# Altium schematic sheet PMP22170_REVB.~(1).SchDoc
size 431 x 279 mm; Date: Not shown in title block; ApprovedBy: Not shown in title block; CheckedBy: Not shown in title block; Author: Not shown in title block; CompanyName: Not shown in title block; Engineer: Not shown in title block; Organization: Not shown in title block; Address1: Not shown in title block; Address2: Not shown in title block; Address3: Not shown in title block; Address4: Not shown in title block; DocumentNumber: 1; Revision: Use project parameter SCH_Rev; SheetNumber: 1; SheetTotal: 1; PageSetup: Record=PageOptions¦CenterHorizontal=True¦CenterVertical=True¦PrintScale=1.00¦XCorrection=1.00¦YCorrection=1.00¦PrintKind=0¦BorderSize=5000000¦LeftOffset=0¦BottomOffset=0¦Orientation=2¦PaperLength=1000¦PaperWidth=1000¦Scale=100¦PaperSource=15¦PrintQuality=600¦MediaType=1¦DitherType=10¦PaperKind=Letter¦PrintScaleMode=1
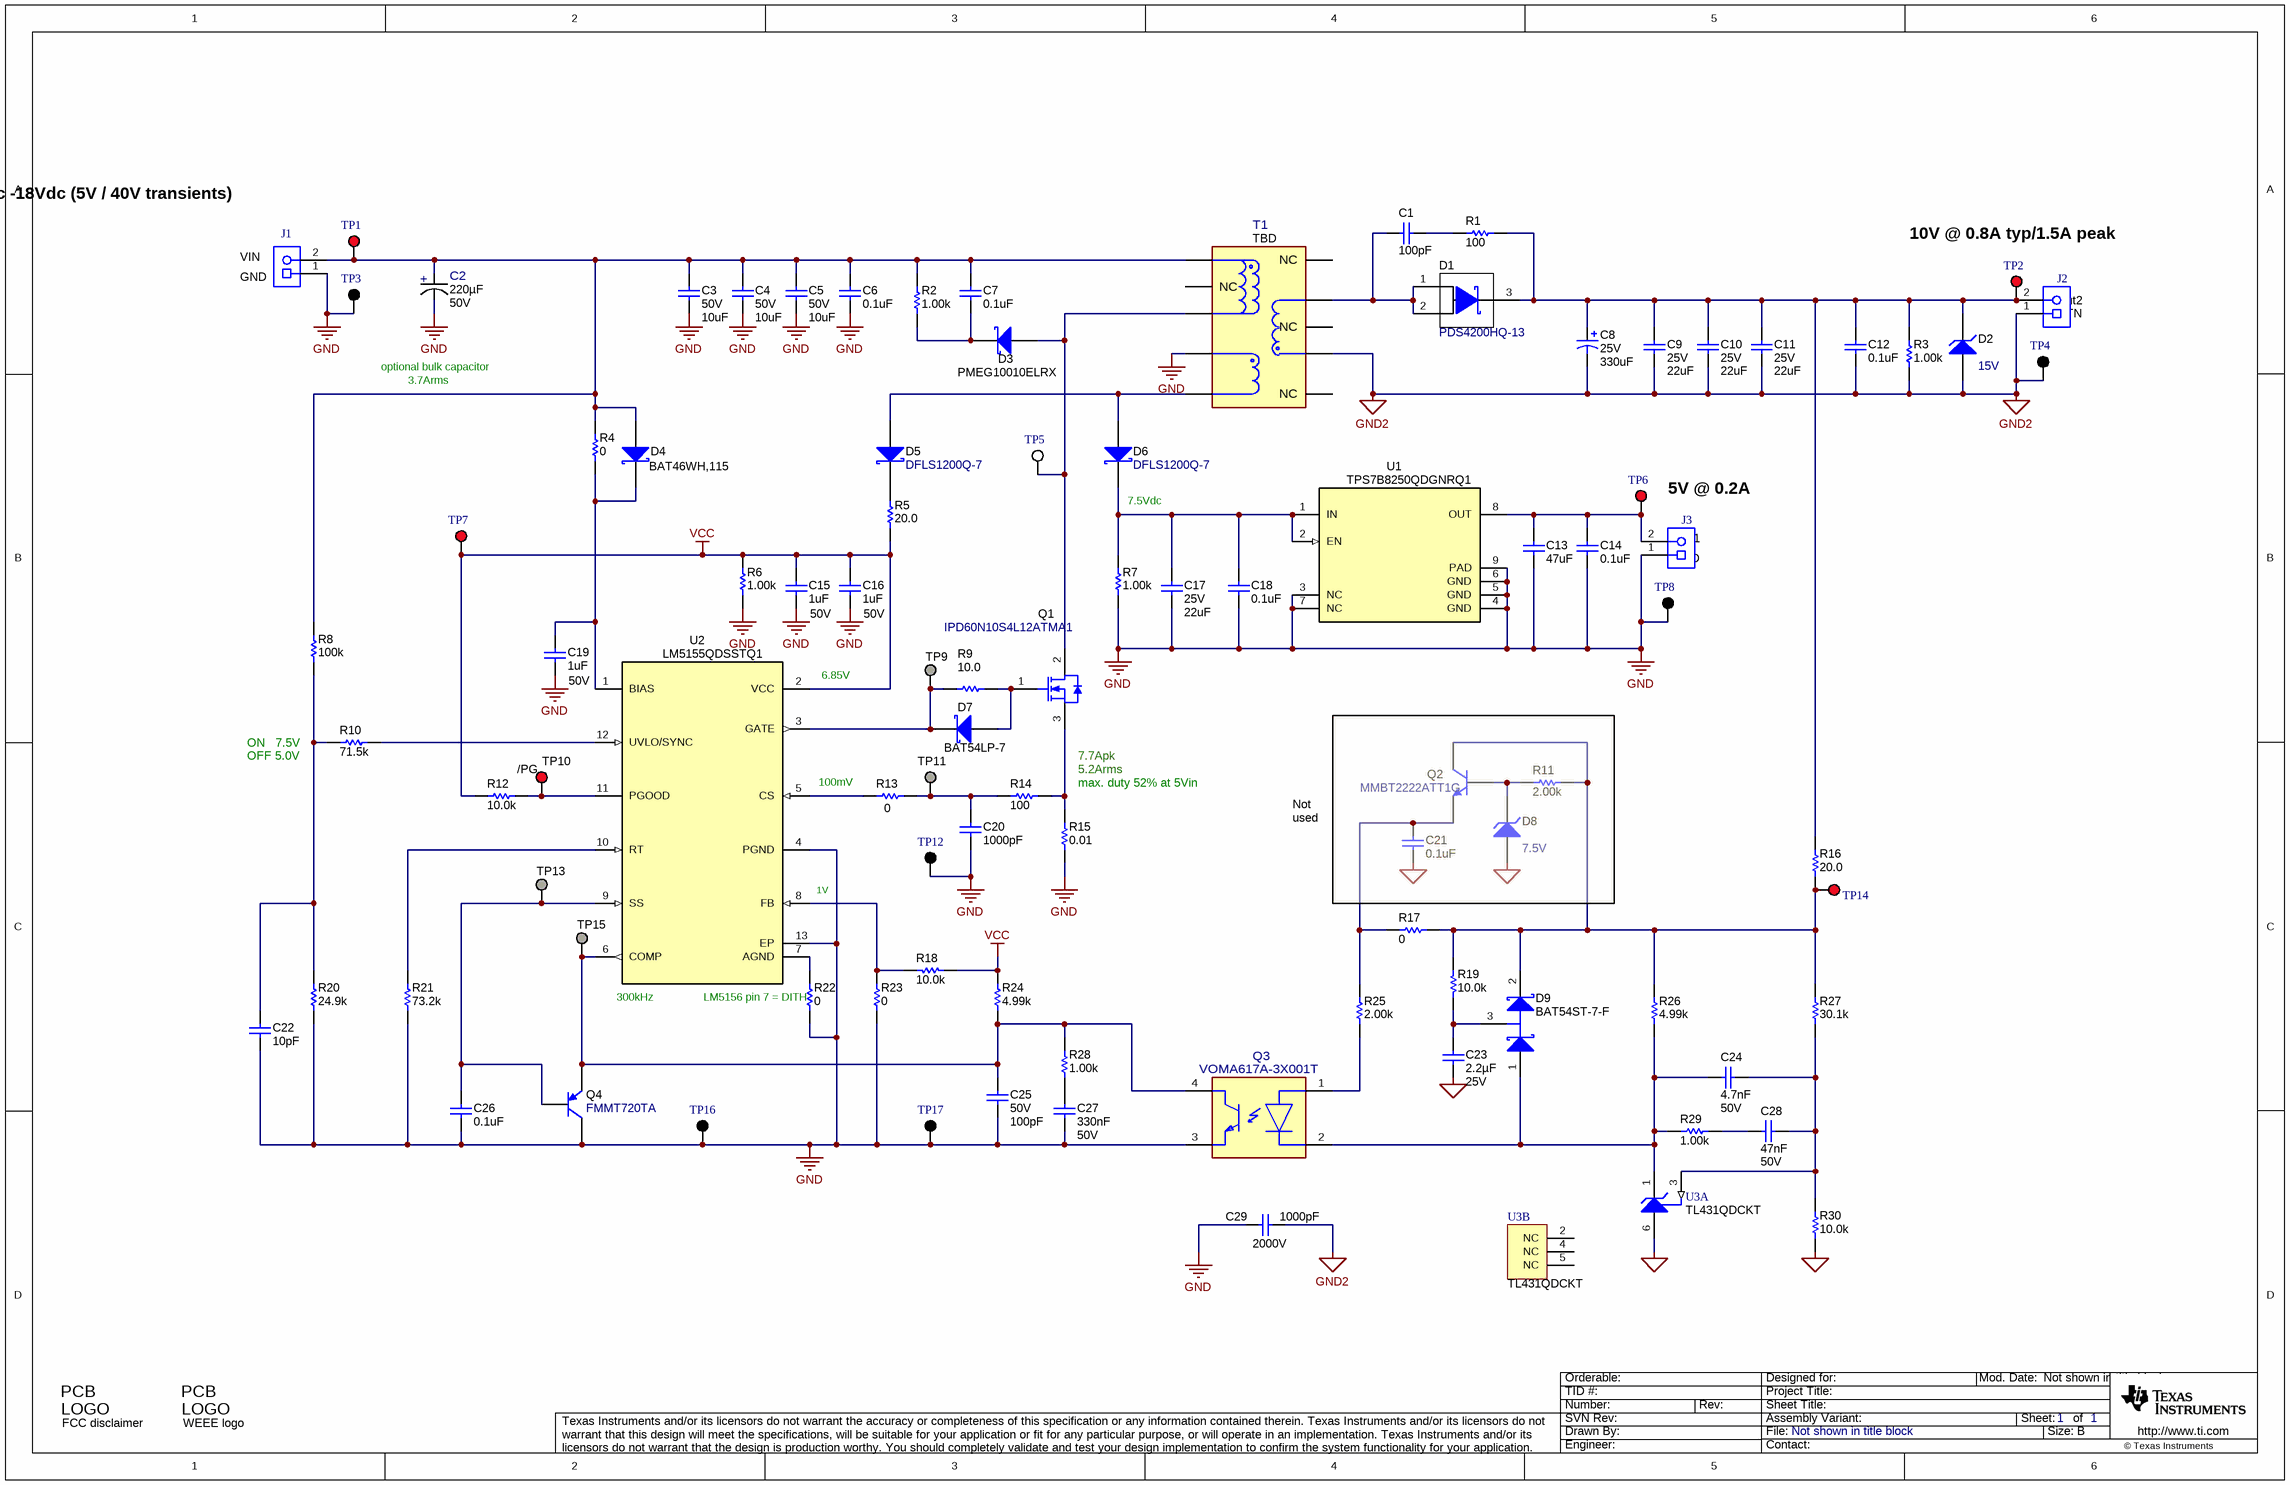
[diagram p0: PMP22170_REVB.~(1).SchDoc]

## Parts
C1  ValueDisplayed: 100pF  [0805_HV]  (hidden comment: Capacitor)
C2  Cap_F: 220µF  VDC_V: 50V  [FP-EEHZS1H221P_RADIAL_SMD-MFG]  (hidden comment: EEH-ZS1H221V)
C3  VDC_V: 50V  ValueDisplayed: 10uF  [1210_280]  (hidden comment: UMK325AB7106KMHT)
C4  VDC_V: 50V  ValueDisplayed: 10uF  [1210_280]  (hidden comment: UMK325AB7106KMHT)
C5  VDC_V: 50V  ValueDisplayed: 10uF  [1210_280]  (hidden comment: UMK325AB7106KMHT)
C6  ValueDisplayed: 0.1uF  [0603]  (hidden comment: Capacitor)
C7  ValueDisplayed: 0.1uF  [0603]  (hidden comment: Capacitor)
C8  VDC_V: 25V  ValueDisplayed: 330uF  [SM_RADIAL_10BMM]  (hidden comment: EEHZC1E331P)
C9  VDC_V: 25V  ValueDisplayed: 22uF  [1210_270]  (hidden comment: TMK325B7226KMHT)
C10  VDC_V: 25V  ValueDisplayed: 22uF  [1210_270]  (hidden comment: TMK325B7226KMHT)
C11  VDC_V: 25V  ValueDisplayed: 22uF  [1210_270]  (hidden comment: TMK325B7226KMHT)
C12  ValueDisplayed: 0.1uF  [0603]  (hidden comment: Capacitor)
C13  ValueDisplayed: 47uF  [1210_270]  (hidden comment: Capacitor)
C14  ValueDisplayed: 0.1uF  [0603]  (hidden comment: Capacitor)
C15  ValueDisplayed: 1uF  Value2: 50V  [0805_HV1]  (hidden comment: Capacitor)
C16  ValueDisplayed: 1uF  Value2: 50V  [0805_HV1]  (hidden comment: Capacitor)
C17  VDC_V: 25V  ValueDisplayed: 22uF  [1210_270]  (hidden comment: TMK325B7226KMHT)
C18  ValueDisplayed: 0.1uF  [0603]  (hidden comment: Capacitor)
C19  ValueDisplayed: 1uF  Value2: 50V  [0805_HV1]  (hidden comment: Capacitor)
C20  ValueDisplayed: 1000pF  [0603]  (hidden comment: Capacitor)
C21  ValueDisplayed: 0.1uF  [0603]  (hidden comment: Capacitor)
C22  ValueDisplayed: 10pF  [0603]  (hidden comment: Capacitor)
C23  Cap_F: 2.2µF  VDC_V: 25V  [0805_HV]  (hidden comment: CGA4J3X7R1E225K125AB)
C24  Cap_F: 4.7nF  VDC_V: 50V  [0603]  (hidden comment: GCM188R71H472KA37D)
C25  VDC_V: 50V  ValueDisplayed: 100pF  [0603]  (hidden comment: GCM1885C1H101JA16J)
C26  ValueDisplayed: 0.1uF  [0603]  (hidden comment: Capacitor)
C27  Cap_F: 330nF  VDC_V: 50V  [0603]  (hidden comment: CGA3E3X7R1H334K080AB)
C28  Cap_F: 47nF  VDC_V: 50V  [0603]  (hidden comment: CGA3E2X7R1H473K080AA)
C29  ValueDisplayed: 1000pF  Value2: 2000V  [1808]  (hidden comment: Capacitor)
D1  PDS4200HQ-13  [POWERDI5]
D2  value 15V  [SOD-123]  (hidden comment: MMSZ5245B-7-F)
D3  PartNumber: PMEG10010ELRX  [SOD-123W]  (hidden comment: DIODE_SCHOTTKY)
D4  PartNumber: BAT46WH,115  [SOD-123F]  (hidden comment: DIODE_SCHOTTKY)
D5  DFLS1200Q-7  [PowerDI123]
D6  DFLS1200Q-7  [PowerDI123]
D7  PartNumber: BAT54LP-7  [X1-DFN1006-2]  (hidden comment: DIODE_SCHOTTKY)
D8  value 7.5V  [SOD-123]  (hidden comment: MMSZ4693-HE3-08)
D9  PartNumber: BAT54ST-7-F  [SOT-523]  (hidden comment: DIODE_BAT54S)
J1  Receptacle_2x1  [TERM_BLK_ED555-2DS]  (value not drawn)
J2  Receptacle_2x1  [TERM_BLK_ED555-2DS]  (value not drawn)
J3  Receptacle_2x1  [TERM_BLK_ED555-2DS]  (value not drawn)
Logo1  FCC disclaimer  [FCC_disclaimer]  (no BOM)
Logo2  WEEE logo  [WEEE_Minimum]  (no BOM)
Q1  IPD60N10S4L12ATMA1  [DPAK]
Q2  MMBT2222ATT1G  [SOT-416]
Q3  VOMA617A-3X001T  [FP-VOMA617A-3X001T_SOP4-MFG]
Q4  FMMT720TA  [SOT-23]
R1  ValueDisplayed: 100  [1206]  (hidden comment: CRCW1206100RFKEAHP)
R2  ValueDisplayed: 1.00k  [1210]  (hidden comment: ERJ14NF1001U)
R3  ValueDisplayed: 1.00k  [1210]  (hidden comment: ERJ14NF1001U)
R4  ValueDisplayed: 0  [0603]  (hidden comment: Resistor)
R5  ValueDisplayed: 20.0  [0805_HV]  (hidden comment: CRCW080520R0FKEA)
R6  ValueDisplayed: 1.00k  [1210]  (hidden comment: ERJ14NF1001U)
R7  ValueDisplayed: 1.00k  [1210]  (hidden comment: ERJ14NF1001U)
R8  ValueDisplayed: 100k  [0603]  (hidden comment: CRCW0603100KFKEA)
R9  ValueDisplayed: 10.0  [0603]  (hidden comment: Resistor)
R10  ValueDisplayed: 71.5k  [0603]  (hidden comment: CRCW060371K5FKEA)
R11  ValueDisplayed: 2.00k  [0603]  (hidden comment: CRCW06032K00FKEA)
R12  ValueDisplayed: 10.0k  [0603]  (hidden comment: CRCW060310K0FKEA)
R13  ValueDisplayed: 0  [0603]  (hidden comment: Resistor)
R14  ValueDisplayed: 100  [0603]  (hidden comment: Resistor)
R15  ValueDisplayed: 0.01  [0612]  (hidden comment: ERJ-B2CFR01V)
R16  ValueDisplayed: 20.0  [0603]  (hidden comment: CRCW060320R0FKEA)
R17  ValueDisplayed: 0  [0603]  (hidden comment: Resistor)
R18  value 10.0k  [0603]  (hidden comment: Resistor)
R19  value 10.0k  [0603]  (hidden comment: Resistor)
R20  ValueDisplayed: 24.9k  [0603]  (hidden comment: CRCW060324K9FKEA)
R21  ValueDisplayed: 73.2k  [0603]  (hidden comment: CRCW060373K2FKEA)
R22  ValueDisplayed: 0  [0603]  (hidden comment: Resistor)
R23  ValueDisplayed: 0  [0603]  (hidden comment: Resistor)
R24  ValueDisplayed: 4.99k  [0603]  (hidden comment: CRCW06034K99FKEA)
R25  ValueDisplayed: 2.00k  [0603]  (hidden comment: CRCW06032K00FKEA)
R26  ValueDisplayed: 4.99k  [0603]  (hidden comment: CRCW06034K99FKEA)
R27  ValueDisplayed: 30.1k  [0603]  (hidden comment: CRCW060330K1FKEA)
R28  ValueDisplayed: 1.00k  [0603]  (hidden comment: CRCW06031K00FKEA)
R29  ValueDisplayed: 1.00k  [0603]  (hidden comment: CRCW06031K00FKEA)
R30  ValueDisplayed: 10.0k  [0603]  (hidden comment: CRCW060310K0FKEA)
T1  PartNumber: TBD  [FP-DR12-C249_SMT_12MM0_14MM5-MFG]
TP1  5000  [Keystone5000]  (value not drawn)
TP2  5000  [Keystone5000]  (value not drawn)
TP3  5001  [Keystone5001]  (value not drawn)
TP4  5001  [Keystone5001]  (value not drawn)
TP5  5002  [Keystone5002]  (value not drawn)
TP6  5000  [Keystone5000]  (value not drawn)
TP7  5000  [Keystone5000]  (value not drawn)
TP8  5001  [Keystone5001]  (value not drawn)
TP9  TP_SM_1MM  [TP_SM_1MM]  (value not drawn)  (no BOM)
TP10  5000  [Keystone5000]  (value not drawn)
TP11  TP_SM_1MM  [TP_SM_1MM]  (value not drawn)  (no BOM)
TP12  5001  [Keystone5001]  (value not drawn)
TP13  TP_SM_1MM  [TP_SM_1MM]  (value not drawn)  (no BOM)
TP14  5000  [Keystone5000]  (value not drawn)
TP15  TP_SM_1MM  [TP_SM_1MM]  (value not drawn)  (no BOM)
TP16  5001  [Keystone5001]  (value not drawn)
TP17  5001  [Keystone5001]  (value not drawn)
U1  TPS7B8250QDGNRQ1  [DGN0008D_N]
U2  LM5155QDSSTQ1  [DSS0012C]
U3  TL431QDCKT  [DCK0006A_N]  (parts A,B of 2)

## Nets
GND: C2.1(CATHODE) C3.2 C4.2 C5.2 C6.2 C13.2 C14.2 C15.2 C16.2 C17.2 C18.2 C19.2 C20.2 C22.2 C25.2 C26.2 C27.2 C29.2 J1.1 J3.1 Q3.3(EMITTER) Q4.3(C) R6.1 R7.1 R15.1 R20.1 R21.1 R22.1 R23.1 T1.2(S3) TP3.1 TP8.1 TP12.1 TP16.1 TP17.1 U1.3(NC) U1.4(GND) U1.5(GND) U1.6(GND) U1.7(NC) U1.9(PAD) U2.4(PGND) U2.13(EP)
GND2: C8.2(-) C9.2 C10.2 C11.2 C12.2 C21.2 C23.2 C29.1 D2.2(A) D8.2(A) J2.1 R3.1 R30.1 T1.9(S4) TP4.1 U3.6(ANODE)
VCC: C15.1 C16.1 R5.1 R6.2 R12.1 R18.2 R24.2 TP7.1 U2.2(VCC)
PG: R12.2 TP10.1 U2.11(PGOOD)
NetC1_1: C1.1 R1.1
NetC1_2: C1.2 D1.1(A) D1.2(A) T1.7
NetC2_2: C2.2(ANODE) C3.1 C4.1 C5.1 C6.1 C7.1 D4.2(A) J1.2 R2.2 R4.2 R8.2 T1.5(S1,S2) TP1.1
NetC7_2: C7.2 D3.1(K) R2.1
NetC8_1: C8.1(+) C9.1 C10.1 C11.1 C12.1 D1.3(K) D2.1(K) J2.2 R1.2 R3.2 R16.2 TP2.1
NetC13_1: C13.1 C14.1 J3.2 TP6.1 U1.8(OUT)
NetC17_1: C17.1 C18.1 D6.1(K) R7.2 U1.1(IN) U1.2(EN)
NetC19_1: C19.1 D4.1(K) R4.1 U2.1(BIAS)
NetC20_1: C20.1 R13.2 R14.1 TP11.1
NetC21_1: C21.1 Q2.2(E) R17.2 R25.2
NetC22_1: C22.1 R8.1 R10.1 R20.2
NetC23_1: C23.1 D9.3(C) R19.1
NetC24_1: C24.1 C28.1 R27.1 R30.2 U3.3(REF)
NetC24_2: C24.2 D9.1(A) Q3.2(CATHODE) R26.1 R29.2 U3.1(CATHODE)
NetC25_1: C25.1 Q3.4(COLLECTOR) Q4.2(E) R24.1 R28.2 TP15.1 U2.6(COMP)
NetC26_1: C26.1 Q4.1(B) TP13.1 U2.9(SS)
NetC27_1: C27.1 R28.1
NetC28_2: C28.2 R29.1
NetD3_2: D3.2(A) Q1.2(D) T1.3 TP5.1
NetD5_1: D5.1(K) R5.2
NetD5_2: D5.2(A) D6.2(A) T1.1
NetD7_1: D7.1(K) R9.2 TP9.1 U2.3(GATE)
NetD7_2: D7.2(A) Q1.1(G) R9.1
NetD8_1: D8.1(K) Q2.1(B) R11.1
NetD9_2: D9.2(K) Q2.3(C) R11.2 R16.1 R17.1 R19.2 R26.2 R27.2 TP14.1
NetQ1_3: Q1.3(S) R14.2 R15.2
NetQ3_1: Q3.1(ANODE) R25.1
NetR10_2: R10.2 U2.12(UVLO/SYNC)
NetR13_1: R13.1 U2.5(CS)
NetR18_1: R18.1 R23.2 U2.8(FB)
NetR21_2: R21.2 U2.10(RT)
NetR22_2: R22.2 U2.7(AGND)

Not connected (* = marked no-connect by the designer): T1 4(NC) 6(NC) 8(NC) 10(NC); U3 2(NC) 4(NC) 5(NC)

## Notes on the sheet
- Input 6Vdc -18Vdc (5V / 40V transients)
- 10V @ 0.8A typ/1.5A peak
- (near J1) VIN
- (near J1) GND
- (near J2) Vout2
- optional bulk capacitor
- RTN
- 3.7Arms
- (near D6) 7.5Vdc
- 5V @ 0.2A
- (near J3) Vout1
- (near J3) GND
- (near U2) 6.85V
- (near R10) ON   7.5V
- (near R10) OFF 5.0V
- (near TP10) /PG
- 7.7Apk
- 5.2Arms
- 100mV
- max. duty 52% at 5Vin
- Not used
- (near U2) 1V
- (near U2) 300kHz
- (near R22) LM5156 pin 7 = DITH

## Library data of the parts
C1 = CMP-0008236-2: CAP, CERM, 100 pF, 250 V, +/- 5%, C0G/NP0, 0805; PartNumber: GRM21A5C2E101JW01D; Manufacturer: MuRata; Polarized: N; Value: 100pF; U/M: EA; Value1: Unknown; VDC_V: 250V; TaMin_C: -55°C; TaMax_C: 125°C; Cap_Case: 0805; SizeArea_mm2: 2.5; SizeAreaWB_mm2: 6.75; SizeX_mm: 2; SizeY_mm: 1.25; SizeZ_mm: 1.45; AEC Category: Q200
C2 = CMP-0087071-1: 220µF 50V Aluminum Polymer Capacitor Radial, Can - SMD 13 mOhm 4000 Hrs @ 125°C; Manufacturer: Panasonic; SizeZ_mm: 16.8mm; AEC Grade: Grade 1; Symbol Name: SYM-EEHZS1H221P; IRMS_A: 3.7A; Tolerance_%: 20%; AEC Qualified: Yes
C3-C5 = CMP-0009258-2: CAP, CERM, 10 uF, 50 V, +/- 10%, X7R, AEC-Q200 Grade 1, 1210; Manufacturer: Taiyo Yuden; TaMin_C: -55°C; Polarized: N; SizeAreaWB_mm2: 14.7; Value1: Unknown; U/M: EA; Value: 10uF; TaMax_C: 125°C; SizeZ_mm: 2.8; SizeX_mm: 3.2; SizeY_mm: 2.5; Cap_Case: 1210; SizeArea_mm2: 8; AEC Qualified: Y; Cap_F: 10µF; AEC Grade: 1; AEC Category: Q200
C6 C7 C12 = CMP-0007144-4: CAP, CERM, 0.1 uF, 50 V, +/- 10%, X7R, 0603; PartNumber: GCM188R71H104KA57D; Manufacturer: MuRata; Polarized: N; Value: 0.1uF; U/M: EA; Cap_F: 100nF; ESR_ohm: 0.02; Value1: 0.02 ohm; VDC_V: 50V; IRMS_A: 1.84A; TaMin_C: -55°C; TaMax_C: 125°C; AEC Category: Q200; SizeArea_mm2: 1.28; SizeAreaWB_mm2: 4.68; SizeX_mm: 1.6; SizeY_mm: 0.8; SizeZ_mm: 1
C8 = CMP-0012593-3: CAP, Polymer Hybrid, 330 uF, 25 V, +/- 20%, 20 ohm, 10x10 SMD; Manufacturer: Panasonic; TaMin_C: -55°C; ESR_ohm: 20; Polarized: Y; SizeAreaWB_mm2: 159.9; Value1: 20 ohm; Value: 330uF; TaMax_C: 125°C; SizeZ_mm: 10.2; SizeX_mm: 11; SizeY_mm: 10.3; SizeArea_mm2: 113.3; CompType: Capacitor; Cap_F: 330µF; IRMS_A: 2A; AEC Category: Q200
C9-C11 C17 = CMP-0009255-2: CAP, CERM, 22 uF, 25 V, +/- 10%, X7R, AEC-Q200 Grade 1, 1210; Manufacturer: Taiyo Yuden; TaMin_C: -55°C; Polarized: N; SizeAreaWB_mm2: 14.7; Value1: Unknown; U/M: EA; Value: 22uF; TaMax_C: 125°C; SizeZ_mm: 2.7; SizeX_mm: 3.2; SizeY_mm: 2.5; Cap_Case: 1210; SizeArea_mm2: 8; AEC Qualified: Y; Cap_F: 22µF; AEC Grade: 1; AEC Category: Q200
C13 = CMP-0009220-2: CAP, CERM, 47 uF, 10 V, +/- 10%, X7R, 1210; PartNumber: GRM32ER71A476KE15L; Manufacturer: MuRata; Polarized: N; Value: 47uF; U/M: EA; Cap_F: 47µF; Value1: Unknown; VDC_V: 10V; TaMin_C: -55°C; TaMax_C: 125°C; Cap_Case: 1210; SizeArea_mm2: 8; SizeAreaWB_mm2: 14.7; SizeX_mm: 3.2; SizeY_mm: 2.5; SizeZ_mm: 2.7; AEC Category: Q200
C14 C18 C21 C26 = CMP-0007378-5: CAP, CERM, 0.1 uF, 16 V, +/- 10%, X7R, 0603; PartNumber: GRM188R71C104KA01D; Manufacturer: MuRata; Polarized: N; Value: 0.1uF; U/M: EA; Cap_F: 100nF; Value1: Unknown; VDC_V: 16V; TaMin_C: -55°C; TaMax_C: 125°C; SizeArea_mm2: 1.28; SizeAreaWB_mm2: 4.68; SizeX_mm: 1.6; SizeY_mm: 0.8; SizeZ_mm: 1; AEC Category: Q200
C15 C16 C19 = CMP-0008350-2: CAP, CERM, 1 uF, 50 V, +/- 10%, X7R, 0805; PartNumber: GRM21BR71H105KA12L; Manufacturer: MuRata; Polarized: N; Value: 1uF; U/M: EA; Cap_F: 1µF; Value1: Unknown; TaMin_C: -55°C; TaMax_C: 125°C; Cap_Case: 0805; SizeArea_mm2: 2.5; SizeAreaWB_mm2: 6.75; SizeX_mm: 2; SizeY_mm: 1.25; SizeZ_mm: 1.45; AEC Category: Q200
C20 = CMP-0007402-4: CAP, CERM, 1000 pF, 25 V, +/- 10%, X7R, 0603; PartNumber: GRM188R71E102KA01D; Manufacturer: MuRata; Polarized: N; Value: 1000pF; U/M: EA; Cap_F: 1nF; Value1: Unknown; VDC_V: 25V; TaMin_C: -55°C; TaMax_C: 125°C; SizeArea_mm2: 1.28; SizeAreaWB_mm2: 4.68; SizeX_mm: 1.6; SizeY_mm: 0.8; SizeZ_mm: 1; AEC Category: Q200
C22 = CMP-0007170-4: CAP, CERM, 10 pF, 50 V, +/- 5%, C0G/NP0, 0603; PartNumber: GRM1885C1H100JA01D; Manufacturer: MuRata; Polarized: N; Value: 10pF; U/M: EA; Value1: Unknown; VDC_V: 50V; TaMin_C: -55°C; TaMax_C: 125°C; SizeArea_mm2: 1.28; SizeAreaWB_mm2: 4.68; SizeX_mm: 1.6; SizeY_mm: 0.8; SizeZ_mm: 1; AEC Category: Q200
C23 = CMP-0007975-2: CAP, CERM, 2.2 uF, 25 V, +/- 10%, X7R, AEC-Q200 Grade 1, 0805; Manufacturer: TDK; TaMin_C: -55°C; Polarized: N; SizeAreaWB_mm2: 6.75; Value1: Unknown; U/M: EA; Value: 2.2uF; TaMax_C: 125°C; SizeZ_mm: 1.45; SizeX_mm: 2; SizeY_mm: 1.25; Cap_Case: 0805; SizeArea_mm2: 2.5; AEC Qualified: Y; AEC Grade: 1; AEC Category: Q200
C24 = CMP-0007146-4: CAP, CERM, 4700 pF, 50 V, +/- 10%, X7R, AEC-Q200 Grade 1, 0603; Manufacturer: MuRata; TaMin_C: -55°C; Polarized: N; SizeAreaWB_mm2: 4.68; Value1: Unknown; U/M: EA; Value: 4700pF; TaMax_C: 125°C; SizeZ_mm: 1; SizeX_mm: 1.6; SizeY_mm: 0.8; SizeArea_mm2: 1.28; AEC Qualified: Y; AEC Category: Q200
C25 = CMP-0750041-1: CAP, CERM, 100 pF, 50 V,+/- 5%, C0G/NP0, AEC-Q200 Grade 1, 0603; Manufacturer: MuRata; AEC Grade: 1; SizeArea_mm2: 1.28; SizeX_mm: 1.6; Polarized: N; TaMax_C: 125°C; Value: 100pF; U/M: EA; AEC Qualified: Y; SizeAreaWB_mm2: 4.68; TaMin_C: -55°C; SizeY_mm: 0.8; AEC Category: Q200
C27 = CMP-0007095-4: CAP, CERM, 0.33 uF, 50 V, +/- 10%, X7R, AEC-Q200 Grade 1, 0603; Manufacturer: TDK; TaMin_C: -55°C; ESR_ohm: 0.01584; Polarized: N; SizeAreaWB_mm2: 4.68; Value1: 0.01584 ohm; U/M: EA; Value: 0.33uF; TaMax_C: 125°C; SizeZ_mm: 1; SizeX_mm: 1.6; SizeY_mm: 0.8; SizeArea_mm2: 1.28; AEC Qualified: Y; IRMS_A: 1.31353A; AEC Category: Q200
C28 = CMP-0007079-4: CAP, CERM, 0.047 uF, 50 V, +/- 10%, X7R, AEC-Q200 Grade 1, 0603; Manufacturer: TDK; TaMin_C: -55°C; ESR_ohm: 0.049007; Polarized: N; SizeAreaWB_mm2: 4.68; Value1: 0.049007 ohm; U/M: EA; TaMax_C: 125°C; SizeZ_mm: 1; SizeX_mm: 1.6; SizeY_mm: 0.8; SizeArea_mm2: 1.28; AEC Qualified: Y; IRMS_A: 767.528mA; AEC Category: Q200
C29 = CMP-0009436-2: CAP, CERM, 1000 pF, 2000 V, +/- 10%, X7R, 1808; PartNumber: GR442QR73D102KW01L; Manufacturer: MuRata; Polarized: N; Value: 1000pF; U/M: EA; Cap_F: 1nF; Value1: Unknown; VDC_V: 2kV; TaMin_C: -55°C; TaMax_C: 125°C; SizeArea_mm2: 9; SizeAreaWB_mm2: 16.5; SizeX_mm: 4.5; SizeY_mm: 2; SizeZ_mm: 2.03; AEC Category: Q200
D1 = CMP-0081019-2: Diode, Schottky, 200 V, 4 A, AEC-Q101, PowerDI5; Manufacturer: Diodes Inc.; Vf_V: 840mV; Io_A: 4A; SizeX_mm: 6.4; Vr_V: 200V; Value2: 0.84V; AEC Category: Q101; TJmax_C: 175°C; SizeAreaWB_mm2: 49.56; SizeArea_mm2: 24.96; Value: 200V; AEC Qualified: Y; SizeY_mm: 3.9; SizeZ_mm: 1.05
D2 = CMP-0005753-1: Diode, Zener, 15 V, 500 mW, SOD-123; Manufacturer: Diodes Inc.; Power_W: 500mW; SizeAreaWB_mm2: 13.095; Value1: 0.5W; RJA_CperW: 350; U/M: EA; SizeZ_mm: 1.35; SizeX_mm: 3.85; SizeY_mm: 1.7; SizeArea_mm2: 6.545; AEC Category: Q101
D3 = CMP-0028782-2: Diode, Schottky, 100 V, 1 A, AEC-Q101, SOD-123W; Manufacturer: Nexperia; Vf_V: 770mV; Value: 100V; Value1: 1A; Value2: 0.77V; TJmax_C: 175°C; SizeAreaWB_mm2: 12.15; SizeArea_mm2: 5.95; SizeX_mm: 3.5; SizeY_mm: 1.7; SizeZ_mm: 1; AEC Category: Q101; AEC Qualified: Y; Green_Lifecycle: Not Set; Green_REACh: Incomplete
D4 = CMP-0028632-2: Diode, Schottky, 100 V, 0.25 A, SOD-123F; Manufacturer: Nexperia; Vf_V: 850mV; Value: 100V; Value1: 0.25A; Value2: 0.85V; Io_A: 250mA; TJmax_C: 150°C; SizeAreaWB_mm2: 11.7; SizeArea_mm2: 5.6; SizeX_mm: 3.5; SizeY_mm: 1.6; SizeZ_mm: 1.1; AEC Category: Q101; Green_Lifecycle: Not Set; Green_REACh: Incomplete
D5 D6 = CMP-0028517-2: Diode, Schottky, 200 V, 1 A, PowerDI123; Manufacturer: Diodes Inc.; Vr_V: 200V; SizeZ_mm: 0.98; Value: 200V; TJmax_C: 175°C; SizeY_mm: 1.78; Vf_V: 850mV; Green_REACh: Passed; Io_A: 1A; Value2: 0.85V; SizeAreaWB_mm2: 13.066; SizeArea_mm2: 6.586; Green_Lifecycle: Active; AEC Category: Q101; SizeX_mm: 3.7; RJC_CperW: 7
D7 = CMP-0076931-2: Diode, Schottky, 30 V, 0.2 A, 1.00x0.50x0.60mm; Manufacturer: Diodes Inc.; Vf_V: 1V; Value: 30V; Value1: 0.2A; Io_A: 200mA; SizeAreaWB_mm2: 3.2; SizeArea_mm2: 0.6; SizeX_mm: 1.0; SizeZ_mm: 0.53; AEC Category: Q101; Green_Lifecycle: Not Set; Green_REACh: Incomplete
D8 = CMP-0077566-3: Diode, Zener, 7.5 V, 500 mW, AEC-Q101, SOD-123; Manufacturer: Vishay-Semiconductor; Power_W: 500mW; SizeZ_mm: 1.35; SizeAreaWB_mm2: 13.095; SizeX_mm: 3.85; AEC Qualified: Y; SizeY_mm: 1.7; Value1: 0.5W; AEC Category: Q101; SizeArea_mm2: 6.545; RJA_CperW: 340
D9 = CMP-0028641-2: Diode, Schottky, 30 V, 0.2 A, SOT-523; Manufacturer: Diodes Inc.; Vf_V: 1V; Value: 30V; Value1: 0.2A; Io_A: 200mA; TJmax_C: 125°C; AEC Category: Q101; Green_Lifecycle: Not Set; Green_REACh: Incomplete; SizeArea_mm2: 2.56; SizeAreaWB_mm2: 6.76; SizeX_mm: 1.6; SizeZ_mm: 0.8
J1-J3 = CMP-0074913-1: Terminal Block, 3.5mm Pitch, 2x1, TH; PartNumber: ED555/2DS; Manufacturer: On-Shore Technology; Cert_CULUS: Y; CNHeader: False; ContactFinish: Brass; CT: True; Current_A: 6A; Gender: Female; Green_Lifecycle: Active; Green_REACh: Passed; Pitch_mm: 3.5; Row_Count: 1; Shrouded: N; Voltage_V: 150V
Logo1 = CMP-0074847-1: FCC_disclaimer; Library Reference: Logo
Logo2 = CMP-0074769-1
Q1 = CMP-0080670-2: MOSFET, N-CH, 100 V, 60 A, AEC-Q101, DPAK; Manufacturer: Infineon Technologies; Alternate Manufacturer: None; QgTyp_nC: 38; AEC Category: Q101; Vgs_V: 16V; Value1: 0.015 ohm; SizeAreaWB_mm2: 101.7114; IdsMax_A: 60A; SizeX_mm: 9.91; SizeArea_mm2: 64.8114; Value: 100V; Value2: 38 nC; Rdson45_ohm: 0.015; SizeY_mm: 6.54; ChType: N; AEC Qualified: Y; ChMode: Enhancement; SizeZ_mm: 2.29
Q2 = CMP-0078773-1: Transistor, NPN, 40 V, 0.6 A, AEC-Q101, SOT-416; Manufacturer: ON Semiconductor; SizeAreaWB_mm2: 6.76; NPN: 1; SizeArea_mm2: 2.56; AEC Qualified: Y; IcRated_A: 600mA; AEC Category: Q101; Value: 40 V; TaMax_C: 150°C; SizeZ_mm: 0.95; PNP: 0; Vceo_V: 40V; TaMin_C: -55°C; SizeY_mm: 1.6; Value1: 0.6 A; CompType: BJT; Vcesat1_V: 300mV; U/M: EA
Q3 = CMP-0087531-1: Optoisolator Transistor Output 3750Vrms 1 Channel 4-SOP; Manufacturer: Vishay; SizeZ_mm: 2.42mm; CTR (Min): 100%; CTR (Max): 200%
Q4 = CMP-0000351-2: Transistor, PNP, 40 V, 1.5 A, AEC-Q101, SOT-23; Manufacturer: Diodes Inc.; TaMax_C: 150°C; Value1: 1.5 A; Vcesat1_V: 26V; SizeX_mm: 2.5; SizeY_mm: 3; TaMin_C: -55°C; IcRated_A: 1.5A; CompType: BJT; SizeZ_mm: 1.1; AEC Qualified: Y; Value: 40 V; SizeArea_mm2: 7.5; NPN: 0; Vceo_V: 40V; PNP: 1; AEC Category: Q101; SizeAreaWB_mm2: 14; U/M: EA
R1 = CMP-0016570-3: RES, 100, 1%, 0.5 W, AEC-Q200 Grade 0, 1206; Manufacturer: Vishay-Dale; Power_W: 500mW; TempCo: 100 ppm/C; Value_Code: 100R; Value: 100; EIA_Code: E96; SizeX_mm: 3.2; SizeY_mm: 1.6; SizeZ_mm: 1.35; Value2: 0.5W; SizeArea_mm2: 5.12; AEC Qualified: Y; AEC Grade: 0; AEC Category: Q200
R2 R3 R6 R7 = CMP-0015030-3: RES, 1.00 k, 1%, 0.5 W, AEC-Q200 Grade 0, 1210; Manufacturer: Panasonic; Power_W: 500mW; TempCo: 100 ppm/C; SizeAreaWB_mm2: 14.7; Value_Code: 1k00; Value: 1.00k; EIA_Code: E96; Res_ohm: 1k; SizeX_mm: 3.2; SizeY_mm: 2.5; SizeZ_mm: 1.35; Value2: 0.5W; SizeArea_mm2: 8; AEC Qualified: Y; VDC_V: 22V; AEC Category: Q200; AEC Grade: 0
R4 R13 R17 R22 R23 = CMP-0025697-4: RES, 0, 5%, 0.1 W, AEC-Q200 Grade 0, 0603; PartNumber: CRCW06030000Z0EA; Manufacturer: Vishay-Dale; Value: 0; Value_Code: 0000; Power_W: 100mW; Value2: 0.1W; VDC_V: 75V; TempCo: 200 ppm/C; SizeArea_mm2: 1.28; SizeX_mm: 1.6; SizeY_mm: 0.8; SizeZ_mm: 1; EIA_Code: E24; AEC Category: Q200; AEC Qualified: Y
R5 = CMP-0021044-3: RES, 20.0, 1%, 0.125 W, AEC-Q200 Grade 0, 0805; Manufacturer: Vishay-Dale; Power_W: 125mW; Value_Code: 20R0; TempCo: 100 ppm/C; Value: 20.0; EIA_Code: E96; Res_ohm: 20; SizeX_mm: 2; SizeY_mm: 1.25; SizeZ_mm: 1.45; Value2: 0.125W; SizeArea_mm2: 2.5; AEC Qualified: Y; VDC_V: 150V; AEC Category: Q200; AEC Grade: 0
R8 = CMP-0021990-4: RES, 100 k, 1%, 0.1 W, AEC-Q200 Grade 0, 0603; Manufacturer: Vishay-Dale; Power_W: 100mW; TempCo: 100 ppm/C; Value: 100k; EIA_Code: E96; SizeX_mm: 1.6; SizeY_mm: 0.8; SizeZ_mm: 1; Value2: 0.1W; SizeArea_mm2: 1.28; AEC Qualified: Y; VDC_V: 75V; AEC Category: Q200; AEC Grade: 0
R9 = CMP-0022003-4: RES, 10.0, 1%, 0.1 W, AEC-Q200 Grade 0, 0603; PartNumber: CRCW060310R0FKEA; Manufacturer: Vishay-Dale; Value: 10.0; Res_ohm: 10; Value_Code: 10R0; Power_W: 100mW; Value2: 0.1W; VDC_V: 75V; TempCo: 100 ppm/C; SizeArea_mm2: 1.28; SizeX_mm: 1.6; SizeY_mm: 0.8; SizeZ_mm: 1; EIA_Code: E96; AEC Category: Q200; AEC Qualified: Y; AEC Grade: 0
R10 = CMP-0022581-4: RES, 71.5 k, 1%, 0.1 W, AEC-Q200 Grade 0, 0603; Manufacturer: Vishay-Dale; Power_W: 100mW; TempCo: 100 ppm/C; Value_Code: 71k5; Value: 71.5k; EIA_Code: E96; SizeX_mm: 1.6; SizeY_mm: 0.8; SizeZ_mm: 1; Value2: 0.1W; SizeArea_mm2: 1.28; AEC Qualified: Y; VDC_V: 75V; AEC Category: Q200; AEC Grade: 0
R11 R25 = CMP-0022268-4: RES, 2.00 k, 1%, 0.1 W, AEC-Q200 Grade 0, 0603; Manufacturer: Vishay-Dale; Power_W: 100mW; TempCo: 100 ppm/C; Value_Code: 2k00; Value: 2.00k; EIA_Code: E96; Res_ohm: 2k; SizeX_mm: 1.6; SizeY_mm: 0.8; SizeZ_mm: 1; Value2: 0.1W; SizeArea_mm2: 1.28; AEC Qualified: Y; VDC_V: 75V; AEC Category: Q200; AEC Grade: 0
R12 R30 = CMP-0021998-4: RES, 10.0 k, 1%, 0.1 W, AEC-Q200 Grade 0, 0603; Manufacturer: Vishay-Dale; Power_W: 100mW; TempCo: 100 ppm/C; Value_Code: 10k0; Value: 10.0k; EIA_Code: E96; Res_ohm: 10k; SizeX_mm: 1.6; SizeY_mm: 0.8; SizeZ_mm: 1; Value2: 0.1W; SizeArea_mm2: 1.28; AEC Qualified: Y; VDC_V: 75V; AEC Category: Q200; AEC Grade: 0
R14 = CMP-0021991-4: RES, 100, 1%, 0.1 W, AEC-Q200 Grade 0, 0603; PartNumber: CRCW0603100RFKEA; Manufacturer: Vishay-Dale; Value: 100; Value_Code: 100R; Power_W: 100mW; Value2: 0.1W; VDC_V: 75V; TempCo: 100 ppm/C; SizeArea_mm2: 1.28; SizeX_mm: 1.6; SizeY_mm: 0.8; SizeZ_mm: 1; EIA_Code: E96; AEC Category: Q200; AEC Qualified: Y; AEC Grade: 0
R15 = CMP-0015054-2: RES, 0.01, 1%, 1 W, AEC-Q200 Grade 0, 0612; Manufacturer: Panasonic; Power_W: 1W; TempCo: 300 ppm/C; SizeAreaWB_mm2: 10.92; Value_Code: R010; U/M: EA; Value: 0.01; EIA_Code: E96; SizeX_mm: 1.6; SizeY_mm: 3.2; SizeZ_mm: 0.85; SizeArea_mm2: 5.12; AEC Qualified: Y; AEC Grade: 0; AEC Category: Q200
R16 = CMP-0022206-4: RES, 20.0, 1%, 0.1 W, AEC-Q200 Grade 0, 0603; Manufacturer: Vishay-Dale; Power_W: 100mW; TempCo: 100 ppm/C; Value_Code: 20R0; Value: 20.0; EIA_Code: E96; Res_ohm: 20; SizeX_mm: 1.6; SizeY_mm: 0.8; SizeZ_mm: 1; Value2: 0.1W; SizeArea_mm2: 1.28; AEC Qualified: Y; VDC_V: 75V; AEC Category: Q200; AEC Grade: 0
R18 R19 = CMP-0021998-4: RES, 10.0 k, 1%, 0.1 W, AEC-Q200 Grade 0, 0603; PartNumber: CRCW060310K0FKEA; Manufacturer: Vishay-Dale; Res_ohm: 10k; Value_Code: 10k0; Power_W: 100mW; Value2: 0.1W; VDC_V: 75V; TempCo: 100 ppm/C; EIA_Code: E96; AEC Category: Q200; AEC Grade: 0; AEC Qualified: Y; SizeArea_mm2: 1.28; SizeX_mm: 1.6; SizeY_mm: 0.8; SizeZ_mm: 1
R20 = CMP-0022237-4: RES, 24.9 k, 1%, 0.1 W, AEC-Q200 Grade 0, 0603; Manufacturer: Vishay-Dale; Power_W: 100mW; TempCo: 100 ppm/C; Value_Code: 24k9; Value: 24.9k; EIA_Code: E96; SizeX_mm: 1.6; SizeY_mm: 0.8; SizeZ_mm: 1; Value2: 0.1W; SizeArea_mm2: 1.28; AEC Qualified: Y; VDC_V: 75V; AEC Category: Q200; AEC Grade: 0
R21 = CMP-0022585-4: RES, 73.2 k, 1%, 0.1 W, AEC-Q200 Grade 0, 0603; Manufacturer: Vishay-Dale; Power_W: 100mW; TempCo: 100 ppm/C; Value_Code: 73k2; Value: 73.2k; EIA_Code: E96; SizeX_mm: 1.6; SizeY_mm: 0.8; SizeZ_mm: 1; Value2: 0.1W; SizeArea_mm2: 1.28; AEC Qualified: Y; VDC_V: 75V; AEC Category: Q200; AEC Grade: 0
R24 R26 = CMP-0022458-4: RES, 4.99 k, 1%, 0.1 W, AEC-Q200 Grade 0, 0603; Manufacturer: Vishay-Dale; Power_W: 100mW; TempCo: 100 ppm/C; Value_Code: 4k99; Value: 4.99k; EIA_Code: E96; SizeX_mm: 1.6; SizeY_mm: 0.8; SizeZ_mm: 1; Value2: 0.1W; SizeArea_mm2: 1.28; AEC Qualified: Y; VDC_V: 75V; AEC Category: Q200; AEC Grade: 0
R27 = CMP-0022324-4: RES, 30.1 k, 1%, 0.1 W, AEC-Q200 Grade 0, 0603; Manufacturer: Vishay-Dale; Power_W: 100mW; TempCo: 100 ppm/C; Value_Code: 30k1; Value: 30.1k; EIA_Code: E96; SizeX_mm: 1.6; SizeY_mm: 0.8; SizeZ_mm: 1; Value2: 0.1W; SizeArea_mm2: 1.28; AEC Qualified: Y; VDC_V: 75V; AEC Category: Q200; AEC Grade: 0
R28 R29 = CMP-0022109-5: RES, 1.00 k, 1%, 0.1 W, AEC-Q200 Grade 0, 0603; Manufacturer: Vishay-Dale; Power_W: 100mW; TempCo: 100 ppm/C; Value_Code: 1k00; Value: 1.00k; EIA_Code: E96; Res_ohm: 1k; SizeX_mm: 1.6; SizeY_mm: 0.8; SizeZ_mm: 1; Value2: 0.1W; SizeArea_mm2: 1.28; AEC Qualified: Y; VDC_V: 75V; AEC Category: Q200; AEC Grade: 0
T1 = CMP-0087431-1: TRANSFORMER, 7uH; Ind_H: 7µH
TP1 TP2 TP6 TP7 TP10 TP14 = CMP-0055137-1: Test Point, Miniature, Red, TH; Manufacturer: Keystone; CNHeader: FALSE; ContactFinish: Silver; CT: TRUE; Green_Lifecycle: Active; Green_REACh: Passed
TP3 TP4 TP8 TP12 TP16 TP17 = CMP-0055138-1: Test Point, Miniature, Black, TH; Manufacturer: Keystone; CNHeader: FALSE; ContactFinish: Silver; CT: TRUE; Green_Lifecycle: Active; Green_REACh: Passed
TP5 = CMP-0055139-1: Test Point, Miniature, White, TH; Manufacturer: Keystone; ContactFinish: Silver; CNHeader: FALSE; CT: TRUE; Green_Lifecycle: Active; Green_REACh: Passed
TP9 TP11 TP13 TP15 = CMP-0003825-1: 1mm Test Point, SMT; Manufacturer: Any
U1 = CMP-0013313-4: 300mA High-Voltage Ultra-Low-Iq Low-Dropout (LDO) Regulator, DGN0008D (VSSOP-8); Manufacturer: Texas Instruments; SizeX_mm: 5.05; SizeY_mm: 3.1; CompType: IC; SizeZ_mm: 1.1; SizeArea_mm2: 15.655; SizeAreaWB_mm2: 35.955; AEC Category: Q200; AEC Qualified: Y
U2 = CMP-0081538-1: Automotive Grade 2.2-MHz Wide Input Non-synchronous Boost Controller, DSS0012C (WSON-12); Alternate PartNumber: LM5155QDSSRQ1; Alternate Manufacturer: Texas Instruments; SizeAreaWB_mm2: 12; SizeZ_mm: 0.8; SizeX_mm: 2; SizeY_mm: 3; SizeArea_mm2: 6; CompType: IC; AEC Qualified: Y; AEC Category: Q200
U3 = CMP-0033197-3: 2% Accuracy Adjustable Precision Shunt Regulator, DCK0006A (SOT-SC70-6); Manufacturer: Texas Instruments; VO Adj(Max)(V): 36; Initial Accuracy @ 25/deg C(%): 2; Eco-Plan: Green (RoHS & no Sb/Br); Iout/Iz(Max)(mA): 100; Rating: Catalog; Temp Coeff(Max)(ppm/ degree C): 92; VO Adj(Min)(V): 2.495; Temp Coeff(Typ)(ppm/ degree C): 34; Min Iz for Regulation(uA): 600; AEC Category: Q200; AEC Qualified: N; CompType: IC; SizeAreaWB_mm2: 9.3; SizeArea_mm2: 4.2; SizeX_mm: 2.1; SizeY_mm: 2.0; SizeZ_mm: 1.1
